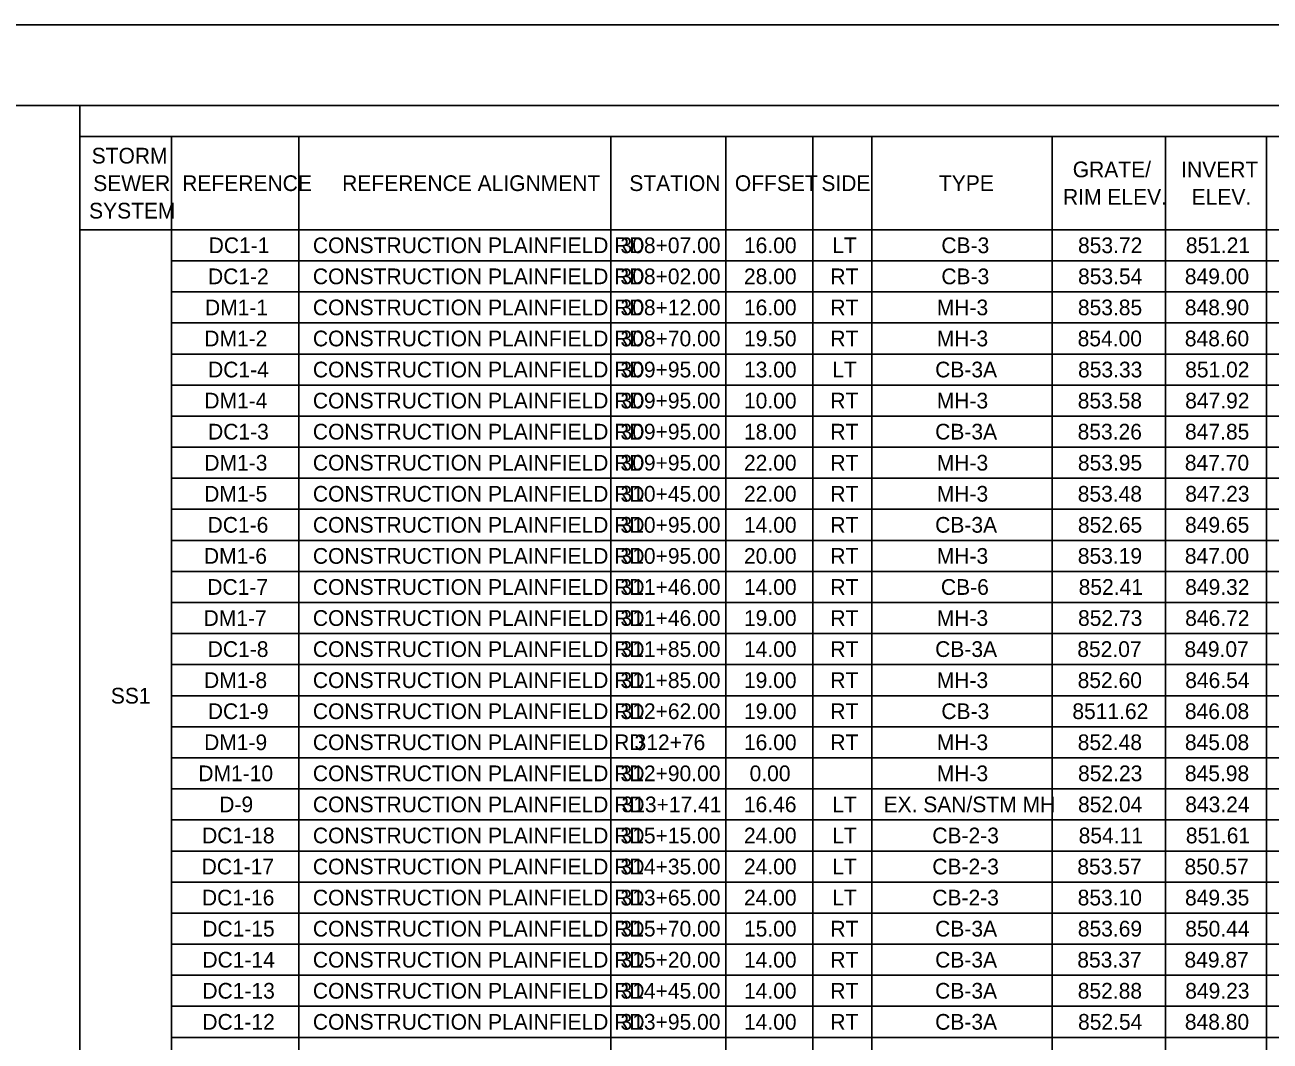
# Model space of a CAD drawing. Extents: x 0 to 34, y 0 to 22.
# Drawn here: x 12.56 to 20.28, y 15.7 to 22 of the extents above; entities that cross this region are included whole.
import ezdxf

# ---------------------------------------------------------------- set-up
doc = ezdxf.new("R2010")
doc.units = 0
for name, color, linetype in [('SH_Border', 7, 'Continuous'), ('SH_Cut_Line', 7, 'Continuous'), ('SH_Text', 7, 'Continuous')]:
    doc.layers.add(name, color=color, linetype=linetype)

msp = doc.modelspace()

# ---------------------------------------------------------------- linework, layer by layer
at = {"layer": 'SH_Border'}
msp.add_lwpolyline([(1.5, 21.5), (33.5, 21.5), (33.5, 0.5), (1.5, 0.5)], close=True, dxfattribs=at)
at = {"layer": 'SH_Cut_Line'}
msp.add_lwpolyline([(0, 0), (34, 0), (34, 22), (0, 22)], close=True, dxfattribs=at)
at = {"layer": 'SH_Text'}
for p, q in [((12.8973, 21.5), (29.6013, 21.5)), ((12.8973, 21.5), (12.8973, 0.4995)), ((12.8973, 21.3073), (29.6013, 21.3073)), ((13.4656, 21.3073), (13.4656, 0.4995)), ((14.2555, 21.3073), (14.2555, 0.4995)), ((16.1918, 21.3073), (16.1918, 0.4995)), ((16.9047, 21.3073), (16.9047, 0.4995)), ((17.4442, 21.3073), (17.4442, 0.4995)), ((17.8102, 21.3073), (17.8102, 0.4995)), ((18.9277, 21.3073), (18.9277, 0.4995)), ((19.6309, 21.3073), (19.6309, 0.4995)), ((20.2571, 21.3073), (20.2571, 0.4995)), ((12.8973, 20.7293), (29.6013, 20.7293)), ((13.4656, 20.5367), (29.6013, 20.5367)), ((13.4656, 20.344), (29.6013, 20.344)), ((13.4656, 20.1513), (29.6013, 20.1513)), ((13.4656, 19.9587), (29.6013, 19.9587)), ((13.4656, 19.766), (29.6013, 19.766)), ((13.4656, 19.5733), (29.6013, 19.5733)), ((13.4656, 19.3807), (29.6013, 19.3807)), ((13.4656, 19.188), (29.6013, 19.188)), ((13.4656, 18.9954), (29.6013, 18.9954)), ((13.4656, 18.8027), (29.6013, 18.8027)), ((13.4656, 18.61), (29.6013, 18.61)), ((13.4656, 18.4174), (29.6013, 18.4174)), ((13.4656, 18.2247), (29.6013, 18.2247)), ((13.4656, 18.032), (29.6013, 18.032)), ((13.4656, 17.8394), (29.6013, 17.8394)), ((13.4656, 17.6467), (29.6013, 17.6467)), ((13.4656, 17.454), (29.6013, 17.454)), ((13.4656, 17.2614), (29.6013, 17.2614)), ((13.4656, 17.0687), (29.6013, 17.0687)), ((13.4656, 16.876), (29.6013, 16.876)), ((13.4656, 16.6834), (29.6013, 16.6834)), ((13.4656, 16.4907), (29.6013, 16.4907)), ((13.4656, 16.298), (29.6013, 16.298)), ((13.4656, 16.1054), (29.6013, 16.1054)), ((13.4656, 15.9127), (29.6013, 15.9127)), ((13.4656, 15.72), (29.6013, 15.72))]:
    msp.add_line(p, q, dxfattribs=at)

# ---------------------------------------------------------------- texts
for s, height, p in [('STORM ', 0.09749, (12.9713, 21.1402)), ('GRATE/ ', 0.09749, (19.0563, 21.0549)), ('INVERT ', 0.09749, (19.729, 21.0549)), ('SEWER ', 0.09749, (12.9808, 20.9696)), ('REFERENCE', 0.09749, (13.533, 20.9696)), ('REFERENCE ALIGNMENT', 0.097489, (14.5249, 20.9696)), ('STATION', 0.09749, (16.3062, 20.9696)), ('OFFSET', 0.09749, (16.9607, 20.9696)), ('SIDE', 0.09749, (17.4974, 20.9696)), ('TYPE', 0.09749, (18.2264, 20.9696)), ('RIM ELEV.', 0.09749, (18.9961, 20.8843)), ('ELEV.', 0.09749, (19.7942, 20.8843)), ('SYSTEM', 0.09749, (12.9554, 20.799)), ('DC1-1', 0.09749, (13.6971, 20.5843)), ('CONSTRUCTION PLAINFIELD RD', 0.097489, (14.3435, 20.5843)), ('308+07.00', 0.09749, (16.2514, 20.5843)), ('16.00', 0.09749, (17.0171, 20.5843)), ('LT', 0.09749, (17.565, 20.5843)), ('CB-3', 0.09749, (18.2415, 20.5843)), ('853.72', 0.09749, (19.089, 20.5843)), ('851.21', 0.09749, (19.7578, 20.5843)), ('DC1-2', 0.09749, (13.693, 20.3916)), ('CONSTRUCTION PLAINFIELD RD', 0.097489, (14.3435, 20.3916)), ('308+02.00', 0.09749, (16.2514, 20.3916)), ('28.00', 0.09749, (17.0171, 20.3916)), ('RT', 0.09749, (17.5529, 20.3916)), ('CB-3', 0.09749, (18.2415, 20.3916)), ('853.54', 0.09749, (19.0893, 20.3916)), ('849.00', 0.09749, (19.7516, 20.3916)), ('DM1-1', 0.09749, (13.6741, 20.1989)), ('CONSTRUCTION PLAINFIELD RD', 0.097489, (14.3435, 20.1989)), ('308+12.00', 0.09749, (16.2514, 20.1989)), ('16.00', 0.09749, (17.0171, 20.1989)), ('RT', 0.09749, (17.5529, 20.1989)), ('MH-3', 0.09749, (18.2131, 20.1989)), ('853.85', 0.09749, (19.0882, 20.1989)), ('848.90', 0.09749, (19.7516, 20.1989)), ('DM1-2', 0.09749, (13.67, 20.0063)), ('CONSTRUCTION PLAINFIELD RD', 0.097489, (14.3435, 20.0063)), ('308+70.00', 0.09749, (16.2514, 20.0063)), ('19.50', 0.09749, (17.0171, 20.0063)), ('RT', 0.09749, (17.5529, 20.0063)), ('MH-3', 0.09749, (18.2131, 20.0063)), ('854.00', 0.09749, (19.0869, 20.0063)), ('848.60', 0.09749, (19.7516, 20.0063)), ('DC1-4', 0.09749, (13.6933, 19.8136)), ('CONSTRUCTION PLAINFIELD RD', 0.097489, (14.3435, 19.8136)), ('309+95.00', 0.09749, (16.2514, 19.8136)), ('13.00', 0.09749, (17.0171, 19.8136)), ('LT', 0.09749, (17.565, 19.8136)), ('CB-3A', 0.09749, (18.2031, 19.8136)), ('853.33', 0.09749, (19.0893, 19.8136)), ('851.02', 0.09749, (19.7537, 19.8136)), ('DM1-4', 0.09749, (13.6703, 19.6209)), ('CONSTRUCTION PLAINFIELD RD', 0.097489, (14.3435, 19.6209)), ('309+95.00', 0.09749, (16.2514, 19.6209)), ('10.00', 0.09749, (17.0171, 19.6209)), ('RT', 0.09749, (17.5529, 19.6209)), ('MH-3', 0.09749, (18.2131, 19.6209)), ('853.58', 0.09749, (19.0873, 19.6209)), ('847.92', 0.09749, (19.7537, 19.6209)), ('DC1-3', 0.09749, (13.6933, 19.4283)), ('CONSTRUCTION PLAINFIELD RD', 0.097489, (14.3435, 19.4283)), ('309+95.00', 0.09749, (16.2514, 19.4283)), ('18.00', 0.09749, (17.0171, 19.4283)), ('RT', 0.09749, (17.5529, 19.4283)), ('CB-3A', 0.09749, (18.2031, 19.4283)), ('853.26', 0.09749, (19.0866, 19.4283)), ('847.85', 0.09749, (19.7529, 19.4283)), ('DM1-3', 0.09749, (13.6703, 19.2356)), ('CONSTRUCTION PLAINFIELD RD', 0.097489, (14.3435, 19.2356)), ('309+95.00', 0.09749, (16.2514, 19.2356)), ('22.00', 0.09749, (17.0171, 19.2356)), ('RT', 0.09749, (17.5529, 19.2356)), ('MH-3', 0.09749, (18.2131, 19.2356)), ('853.95', 0.09749, (19.0882, 19.2356)), ('847.70', 0.09749, (19.7516, 19.2356)), ('DM1-5', 0.09749, (13.6692, 19.0429)), ('CONSTRUCTION PLAINFIELD RD', 0.097489, (14.3435, 19.0429)), ('310+45.00', 0.09749, (16.2514, 19.0429)), ('22.00', 0.09749, (17.0171, 19.0429)), ('RT', 0.09749, (17.5529, 19.0429)), ('MH-3', 0.09749, (18.2131, 19.0429)), ('853.48', 0.09749, (19.0873, 19.0429)), ('847.23', 0.09749, (19.754, 19.0429)), ('DC1-6', 0.09749, (13.6905, 18.8503)), ('CONSTRUCTION PLAINFIELD RD', 0.097489, (14.3435, 18.8503)), ('310+95.00', 0.09749, (16.2514, 18.8503)), ('14.00', 0.09749, (17.0171, 18.8503)), ('RT', 0.09749, (17.5529, 18.8503)), ('CB-3A', 0.09749, (18.2031, 18.8503)), ('852.65', 0.09749, (19.0882, 18.8503)), ('849.65', 0.09749, (19.7529, 18.8503)), ('DM1-6', 0.09749, (13.6676, 18.6576)), ('CONSTRUCTION PLAINFIELD RD', 0.097489, (14.3435, 18.6576)), ('310+95.00', 0.09749, (16.2514, 18.6576)), ('20.00', 0.09749, (17.0171, 18.6576)), ('RT', 0.09749, (17.5529, 18.6576)), ('MH-3', 0.09749, (18.2131, 18.6576)), ('853.19', 0.09749, (19.0878, 18.6576)), ('847.00', 0.09749, (19.7516, 18.6576)), ('DC1-7', 0.09749, (13.6887, 18.4649)), ('CONSTRUCTION PLAINFIELD RD', 0.097489, (14.3435, 18.4649)), ('311+46.00', 0.09749, (16.2514, 18.4649)), ('14.00', 0.09749, (17.0171, 18.4649)), ('RT', 0.09749, (17.5529, 18.4649)), ('CB-6', 0.09749, (18.2388, 18.4649)), ('852.41', 0.09749, (19.0931, 18.4649)), ('849.32', 0.09749, (19.7537, 18.4649)), ('DM1-7', 0.09749, (13.6657, 18.2723)), ('CONSTRUCTION PLAINFIELD RD', 0.097489, (14.3435, 18.2723)), ('311+46.00', 0.09749, (16.2514, 18.2723)), ('19.00', 0.09749, (17.0171, 18.2723)), ('RT', 0.09749, (17.5529, 18.2723)), ('MH-3', 0.09749, (18.2131, 18.2723)), ('852.73', 0.09749, (19.0893, 18.2723)), ('846.72', 0.09749, (19.7537, 18.2723)), ('DC1-8', 0.09749, (13.6913, 18.0796)), ('CONSTRUCTION PLAINFIELD RD', 0.097489, (14.3435, 18.0796)), ('311+85.00', 0.09749, (16.2514, 18.0796)), ('14.00', 0.09749, (17.0171, 18.0796)), ('RT', 0.09749, (17.5529, 18.0796)), ('CB-3A', 0.09749, (18.2031, 18.0796)), ('852.07', 0.09749, (19.0847, 18.0796)), ('849.07', 0.09749, (19.7494, 18.0796)), ('DM1-8', 0.09749, (13.6683, 17.887)), ('CONSTRUCTION PLAINFIELD RD', 0.097489, (14.3435, 17.887)), ('311+85.00', 0.09749, (16.2514, 17.887)), ('19.00', 0.09749, (17.0171, 17.887)), ('RT', 0.09749, (17.5529, 17.887)), ('MH-3', 0.09749, (18.2131, 17.887)), ('852.60', 0.09749, (19.0869, 17.887)), ('846.54', 0.09749, (19.754, 17.887)), ('SS1', 0.09749, (13.0902, 17.7906)), ('DC1-9', 0.09749, (13.6918, 17.6943)), ('CONSTRUCTION PLAINFIELD RD', 0.097489, (14.3435, 17.6943)), ('312+62.00', 0.09749, (16.2514, 17.6943)), ('19.00', 0.09749, (17.0171, 17.6943)), ('RT', 0.09749, (17.5529, 17.6943)), ('CB-3', 0.09749, (18.2415, 17.6943)), ('8511.62', 0.09749, (19.054, 17.6943)), ('846.08', 0.09749, (19.752, 17.6943)), ('DM1-9', 0.09749, (13.6688, 17.5016)), ('CONSTRUCTION PLAINFIELD RD', 0.097489, (14.3435, 17.5016)), ('312+76', 0.09749, (16.3386, 17.5016)), ('16.00', 0.09749, (17.0171, 17.5016)), ('RT', 0.09749, (17.5529, 17.5016)), ('MH-3', 0.09749, (18.2131, 17.5016)), ('852.48', 0.09749, (19.0873, 17.5016)), ('845.08', 0.09749, (19.752, 17.5016)), ('DM1-10', 0.09749, (13.6329, 17.309)), ('CONSTRUCTION PLAINFIELD RD', 0.097489, (14.3435, 17.309)), ('312+90.00', 0.09749, (16.2514, 17.309)), ('0.00', 0.09749, (17.0521, 17.309)), ('MH-3', 0.09749, (18.2131, 17.309)), ('852.23', 0.09749, (19.0893, 17.309)), ('845.98', 0.09749, (19.752, 17.309)), ('D-9', 0.09749, (13.7629, 17.1163)), ('CONSTRUCTION PLAINFIELD RD', 0.097489, (14.3435, 17.1163)), ('313+17.41', 0.09749, (16.2576, 17.1163)), ('16.46', 0.09749, (17.0167, 17.1163)), ('LT', 0.09749, (17.565, 17.1163)), ('EX. SAN/STM MH', 0.097489, (17.8829, 17.1163)), ('852.04', 0.09749, (19.0893, 17.1163)), ('843.24', 0.09749, (19.754, 17.1163)), ('DC1-18', 0.09749, (13.6563, 16.9236)), ('CONSTRUCTION PLAINFIELD RD', 0.097489, (14.3435, 16.9236)), ('315+15.00', 0.09749, (16.2514, 16.9236)), ('24.00', 0.09749, (17.0171, 16.9236)), ('LT', 0.09749, (17.565, 16.9236)), ('CB-2-3', 0.09749, (18.1854, 16.9236)), ('854.11', 0.09749, (19.0931, 16.9236)), ('851.61', 0.09749, (19.7578, 16.9236)), ('DC1-17', 0.09749, (13.6537, 16.731)), ('CONSTRUCTION PLAINFIELD RD', 0.097489, (14.3435, 16.731)), ('314+35.00', 0.09749, (16.2514, 16.731)), ('24.00', 0.09749, (17.0171, 16.731)), ('LT', 0.09749, (17.565, 16.731)), ('CB-2-3', 0.09749, (18.1854, 16.731)), ('853.57', 0.09749, (19.0847, 16.731)), ('850.57', 0.09749, (19.7494, 16.731)), ('DC1-16', 0.09749, (13.6555, 16.5383)), ('CONSTRUCTION PLAINFIELD RD', 0.097489, (14.3435, 16.5383)), ('313+65.00', 0.09749, (16.2514, 16.5383)), ('24.00', 0.09749, (17.0171, 16.5383)), ('LT', 0.09749, (17.565, 16.5383)), ('CB-2-3', 0.09749, (18.1854, 16.5383)), ('853.10', 0.09749, (19.0869, 16.5383)), ('849.35', 0.09749, (19.7529, 16.5383)), ('DC1-15', 0.09749, (13.6572, 16.3456)), ('CONSTRUCTION PLAINFIELD RD', 0.097489, (14.3435, 16.3456)), ('315+70.00', 0.09749, (16.2514, 16.3456)), ('15.00', 0.09749, (17.0171, 16.3456)), ('RT', 0.09749, (17.5529, 16.3456)), ('CB-3A', 0.09749, (18.2031, 16.3456)), ('853.69', 0.09749, (19.0878, 16.3456)), ('850.44', 0.09749, (19.754, 16.3456)), ('DC1-14', 0.09749, (13.6582, 16.153)), ('CONSTRUCTION PLAINFIELD RD', 0.097489, (14.3435, 16.153)), ('315+20.00', 0.09749, (16.2514, 16.153)), ('14.00', 0.09749, (17.0171, 16.153)), ('RT', 0.09749, (17.5529, 16.153)), ('CB-3A', 0.09749, (18.2031, 16.153)), ('853.37', 0.09749, (19.0847, 16.153)), ('849.87', 0.09749, (19.7494, 16.153)), ('DC1-13', 0.09749, (13.6582, 15.9603)), ('CONSTRUCTION PLAINFIELD RD', 0.097489, (14.3435, 15.9603)), ('314+45.00', 0.09749, (16.2514, 15.9603)), ('14.00', 0.09749, (17.0171, 15.9603)), ('RT', 0.09749, (17.5529, 15.9603)), ('CB-3A', 0.09749, (18.2031, 15.9603)), ('852.88', 0.09749, (19.0873, 15.9603)), ('849.23', 0.09749, (19.754, 15.9603)), ('DC1-12', 0.09749, (13.658, 15.7676)), ('CONSTRUCTION PLAINFIELD RD', 0.097489, (14.3435, 15.7676)), ('313+95.00', 0.09749, (16.2514, 15.7676)), ('14.00', 0.09749, (17.0171, 15.7676)), ('RT', 0.09749, (17.5529, 15.7676)), ('CB-3A', 0.09749, (18.2031, 15.7676)), ('852.54', 0.09749, (19.0893, 15.7676)), ('848.80', 0.09749, (19.7516, 15.7676))]:
    msp.add_text(s, height=height, dxfattribs=at).set_placement(p)

doc.saveas('drawing.dxf')
